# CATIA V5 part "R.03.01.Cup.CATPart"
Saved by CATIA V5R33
Part number: R.03.01.Cup
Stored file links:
  C:\Users\Ryzen5700u\Desktop\robot_cicloidale_singolo\Assieme_robot_cicloidale_singolo\R.03.01.Cup.CATPart

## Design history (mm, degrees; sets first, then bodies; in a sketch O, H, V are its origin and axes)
Body1 "Solid1" (main body)
  Solid1: solid without history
